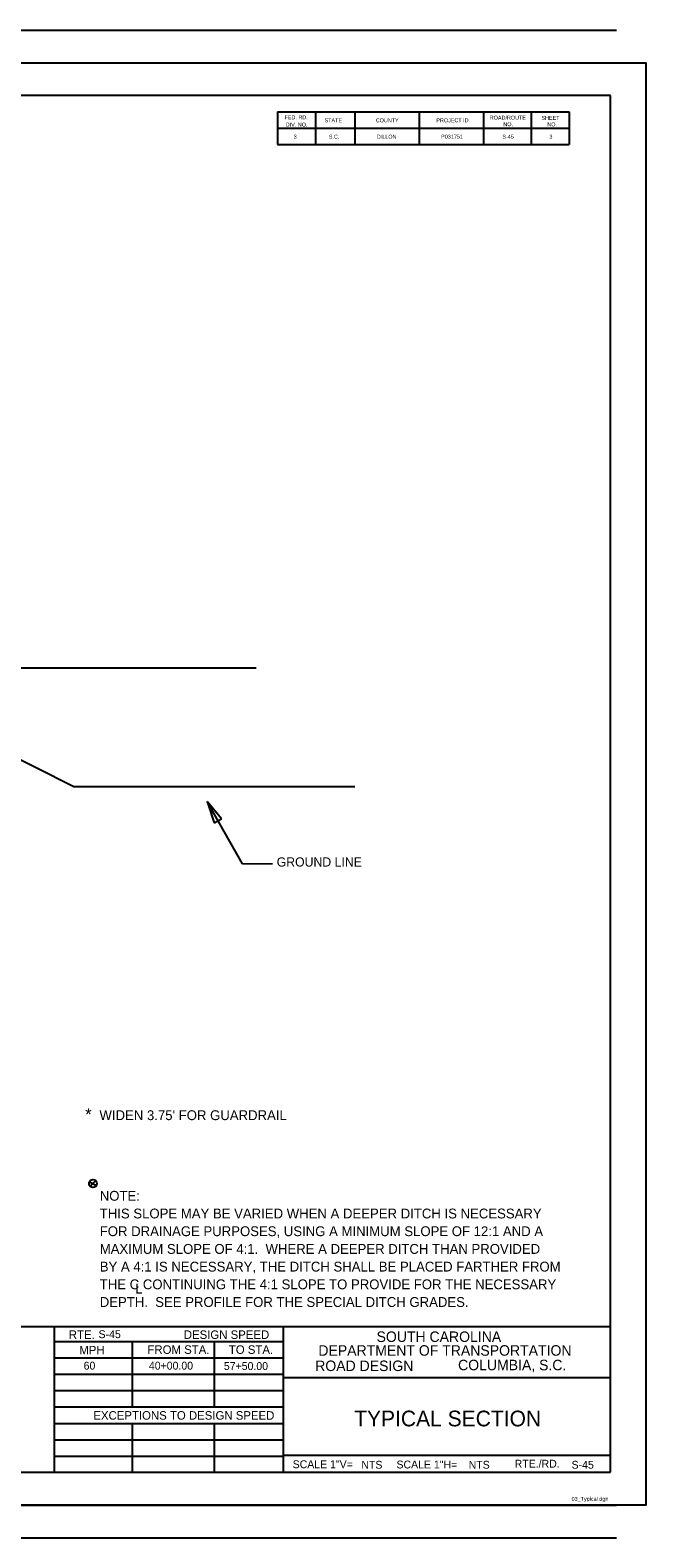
# Model space of a CAD drawing. Extents: x -9123 to -7163, y 44168 to 46468.
# Drawn here: x -7633 to -7163, y 44168 to 45318 of the extents above; entities that cross this region are included whole.
import ezdxf

# ---------------------------------------------------------------- set-up
doc = ezdxf.new("R2010")
doc.units = 0
for name, color, linetype in [('RD_SHT_Bndy', 7, 'Continuous'), ('RD_SHT_IplotShp', 7, 'Continuous'), ('RD_SHT_Snap', 7, 'Continuous'), ('RD_SHT_TX', 7, 'Continuous'), ('RD_TX_TypSect', 7, 'Continuous')]:
    doc.layers.add(name, color=color, linetype=linetype)

msp = doc.modelspace()

# ---------------------------------------------------------------- linework, layer by layer
at = {"layer": 'RD_SHT_Bndy'}
for p, q in [((-8945.7, 45318), (-7185.7, 45318)), ((-8945.7, 45318), (-7185.7, 45318)), ((-8945.7, 45293), (-7185.7, 45293)), ((-7190.2, 45268), (-8865.2, 45268)), ((-7190.2, 44218), (-7190.2, 45268)), ((-7444.2, 45255.7), (-7444.2, 45230.7)), ((-7444.2, 45255.7), (-7221.7, 45255.7)), ((-7415.2, 45255.7), (-7415.2, 45230.7)), ((-7385.2, 45255.7), (-7385.2, 45230.7)), ((-7336.2, 45255.7), (-7336.2, 45230.7)), ((-7287.2, 45255.7), (-7287.2, 45230.7)), ((-7250.7, 45255.7), (-7250.7, 45230.7)), ((-7221.7, 45255.7), (-7221.7, 45230.7)), ((-7444.2, 45243.2), (-7221.7, 45243.2)), ((-7444.2, 45230.7), (-7221.7, 45230.7)), ((-7810.4, 44329.1), (-7614.8, 44329.1)), ((-7614.8, 44329.1), (-7614.8, 44218)), ((-7614.8, 44329.1), (-7439.8, 44329.1)), ((-7439.8, 44218), (-7439.8, 44329.1)), ((-7439.8, 44329.1), (-7190.2, 44329.1)), ((-7439.8, 44329.1), (-7439.8, 44329.1)), ((-7614.8, 44317.8), (-7439.8, 44317.8)), ((-7554.8, 44280.3), (-7554.8, 44317.8)), ((-7492.3, 44280.3), (-7492.3, 44317.8)), ((-7439.8, 44314.7), (-7439.8, 44314.7)), ((-7614.8, 44305.3), (-7439.8, 44305.3)), ((-7614.8, 44292.8), (-7439.8, 44292.8)), ((-7439.8, 44290.3), (-7190.2, 44290.3)), ((-7614.8, 44280.3), (-7439.8, 44280.3)), ((-7554.8, 44267.8), (-7554.8, 44280.3)), ((-7492.3, 44267.8), (-7492.3, 44280.3)), ((-7439.8, 44280.3), (-7439.8, 44280.3)), ((-7614.8, 44267.8), (-7439.8, 44267.8)), ((-7614.8, 44255.3), (-7439.8, 44255.3)), ((-7554.8, 44218), (-7554.8, 44255.3)), ((-7492.3, 44218), (-7492.3, 44255.3)), ((-7614.8, 44242.8), (-7439.8, 44242.8)), ((-7614.8, 44230.3), (-7439.8, 44230.3)), ((-7439.8, 44231.1), (-7190.2, 44231.1)), ((-8865.2, 44218), (-7190.2, 44218)), ((-7439.8, 44218), (-7190.2, 44218)), ((-8945.7, 44193), (-7185.7, 44193)), ((-8945.7, 44168), (-7185.7, 44168))]:
    msp.add_line(p, q, dxfattribs=at)
at = {"layer": 'RD_SHT_IplotShp'}
msp.add_lwpolyline([(-8959.2, 45293), (-7163.2, 45293), (-7163.2, 44193), (-8959.2, 44193)], close=True, dxfattribs=at)
at = {"layer": 'RD_SHT_Snap'}
msp.add_line((-7163.2, 45293), (-7163.2, 44193), dxfattribs=at)
at = {"layer": 'RD_TX_TypSect'}
for p, q in [((-7890.7, 44831.6), (-7460.5, 44831.6)), ((-7720, 44801.2), (-7599.7, 44741.1)), ((-7599.7, 44741.1), (-7385.2, 44741.1)), ((-7470.9, 44682.2), (-7497.9, 44729.6)), ((-7497.9, 44729.6), (-7492.6, 44713.3)), ((-7487.1, 44716.3), (-7497.9, 44729.6)), ((-7492.6, 44713.3), (-7487.1, 44716.3)), ((-7470.9, 44682.2), (-7448, 44682.3)), ((-7587.8, 44439.6), (-7582.5, 44436.8)), ((-7587.2, 44436.1), (-7583.1, 44440.3))]:
    msp.add_line(p, q, dxfattribs=at)
msp.add_circle((-7585.1, 44438.2), 3, dxfattribs=at)

# ---------------------------------------------------------------- texts
at = {"layer": 'RD_SHT_TX'}
for s, height, p in [('FED. RD.', 3, (-7438.9, 45250)), ('ROAD/ROUTE', 3, (-7282.3, 45249.7)), ('SHEET', 3, (-7242.9, 45249.5)), ('DIV. NO.', 3, (-7438, 45244.4)), ('STATE', 3, (-7408.4, 45247.7)), ('COUNTY', 3, (-7369.3, 45247.7)), ('PROJECT ID', 3, (-7323.1, 45247.7)), ('         NO.', 3, (-7282.3, 45244.7)), ('NO.', 3, (-7238.4, 45244.6)), ('3', 3, (-7431.9, 45235.2)), ('S.C.', 3, (-7405.1, 45235.2)), ('DILLON', 3, (-7368.5, 45235.2)), ('P031751', 3, (-7319.4, 45235.2)), ('S-45', 3, (-7272.7, 45235.2)), ('3', 3, (-7236.8, 45235.2)), ('*', 9.38, (-7591, 44486.3)), ('RTE.', 6.5, (-7603.5, 44319.7)), ('S-45', 6, (-7580.8, 44320.3)), ('DESIGN SPEED', 6.5, (-7515.8, 44319.7)), ('SOUTH CAROLINA', 8, (-7368.7, 44317.4)), ('MPH', 6.5, (-7595.5, 44307.9)), ('FROM STA.', 6.5, (-7543.5, 44308.3)), ('TO STA.', 6.5, (-7481.4, 44308.3)), ('DEPARTMENT OF TRANSPORTATION', 8, (-7413.1, 44306.9)), ('60', 6, (-7592.2, 44296.3)), ('40+00.00', 6, (-7542.4, 44296.3)), ('57+50.00', 6, (-7485.2, 44296)), ('ROAD DESIGN', 8, (-7415.5, 44295.2)), ('COLUMBIA, S.C.', 8, (-7306.5, 44295.8)), ('EXCEPTIONS TO DESIGN SPEED', 6.5, (-7584.8, 44258.1)), ('TYPICAL SECTION', 12, (-7385.8, 44253)), ('SCALE 1"V=', 6, (-7432.7, 44221.1)), ('NTS', 6, (-7380.3, 44220.7)), ('SCALE 1"H=', 6, (-7353.5, 44220.9)), ('NTS', 6, (-7298.4, 44220.7)), ('RTE./RD.', 6, (-7263.3, 44221.5)), ('S-45', 6, (-7219.9, 44220.7)), ('03_Typical.dgn', 3, (-7219.9, 44196.2))]:
    msp.add_text(s, height=height, dxfattribs=at).set_placement(p)
at = {"layer": 'RD_TX_TypSect'}
for s, height, p in [('GROUND LINE', 7, (-7444.9, 44680)), ("WIDEN 3.75' FOR GUARDRAIL ", 7.5, (-7580.1, 44486.6)), ('NOTE:', 7.5, (-7579.9, 44425.1)), ('THIS SLOPE MAY BE VARIED WHEN A DEEPER DITCH IS NECESSARY', 7.5, (-7579.9, 44411.6)), ('FOR DRAINAGE PURPOSES, USING A MINIMUM SLOPE OF 12:1 AND A', 7.5, (-7579.9, 44398.1)), ('MAXIMUM SLOPE OF 4:1.  WHERE A DEEPER DITCH THAN PROVIDED', 7.5, (-7579.9, 44384.6)), ('BY A 4:1 IS NECESSARY, THE DITCH SHALL BE PLACED FARTHER FROM', 7.5, (-7579.9, 44371.1)), ('THE C CONTINUING THE 4:1 SLOPE TO PROVIDE FOR THE NECESSARY', 7.5, (-7579.9, 44357.6)), ('L', 7.5, (-7552.8, 44354.3)), ('DEPTH.  SEE PROFILE FOR THE SPECIAL DITCH GRADES.', 7.5, (-7579.9, 44344.1))]:
    msp.add_text(s, height=height, dxfattribs=at).set_placement(p)

doc.saveas('drawing.dxf')
